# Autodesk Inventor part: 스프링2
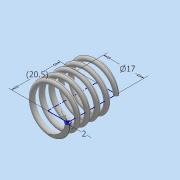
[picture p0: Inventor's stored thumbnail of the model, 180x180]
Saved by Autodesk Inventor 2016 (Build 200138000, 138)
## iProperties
Created: 2019-11
Part Number: 스프링2
Material: 일반
Document SubType Name: Modeling
Designer: user
Density: 1 g/cm^3
Appearance: 기본값
Mass: 0.822006 g
Surface Area: 16.7268 cm^2
Volume: 0.822006 cm^3
Author: user
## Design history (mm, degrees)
sketch "스케치1"
  geometry: L1 (0, 0)-(8.5, 0); L2 (8.5, 0)-(8.5, 20.5); L3 (8.5, 20.5)-(0, 20.5); L4 (0, 20.5)-(0, 0); C1 r 1 at (8.5, 0)
  constraints: 8 end point, 2 parallel, 1 centre point, 1 coincident, 1 horizontal, 1 perpendicular
  dimensions: "d1" = 17 diameter of L2 L4; "d2" = 2 diameter of C1; "d3" = 20.5 distance of L3.end L1.start (derived)
feature "코일1" sketch "스케치1" pitch "d4" = 10; turns "d6" = 5; dims "d5" = 20.5 (= d3), "d7" = 0, angle "d8" = 90 deg, angle "d9" = 90 deg, "d10" = 0, "d11" = 0
sketch "스케치2"
  geometry: L1 (-15, 20.5)-(15, 20.5); L2 (15, 20.5)-(15, 0); L3 (15, 0)-(-15, 0); L4 (-15, 0)-(-15, 20.5); 2 further points
  constraints: 8 end point, 2 parallel, 1 coincident, 1 horizontal, 1 midpoint, 1 perpendicular
  dimensions: "d12" = 20.5 distance of L3.end L1.start (= d3); "d13" = 30 distance of L1.start L1.end
extrude "돌출1" sketch "스케치2" stored distance "d14" = 117.5; taper "d15" = 0 deg
node "솔리드1"
